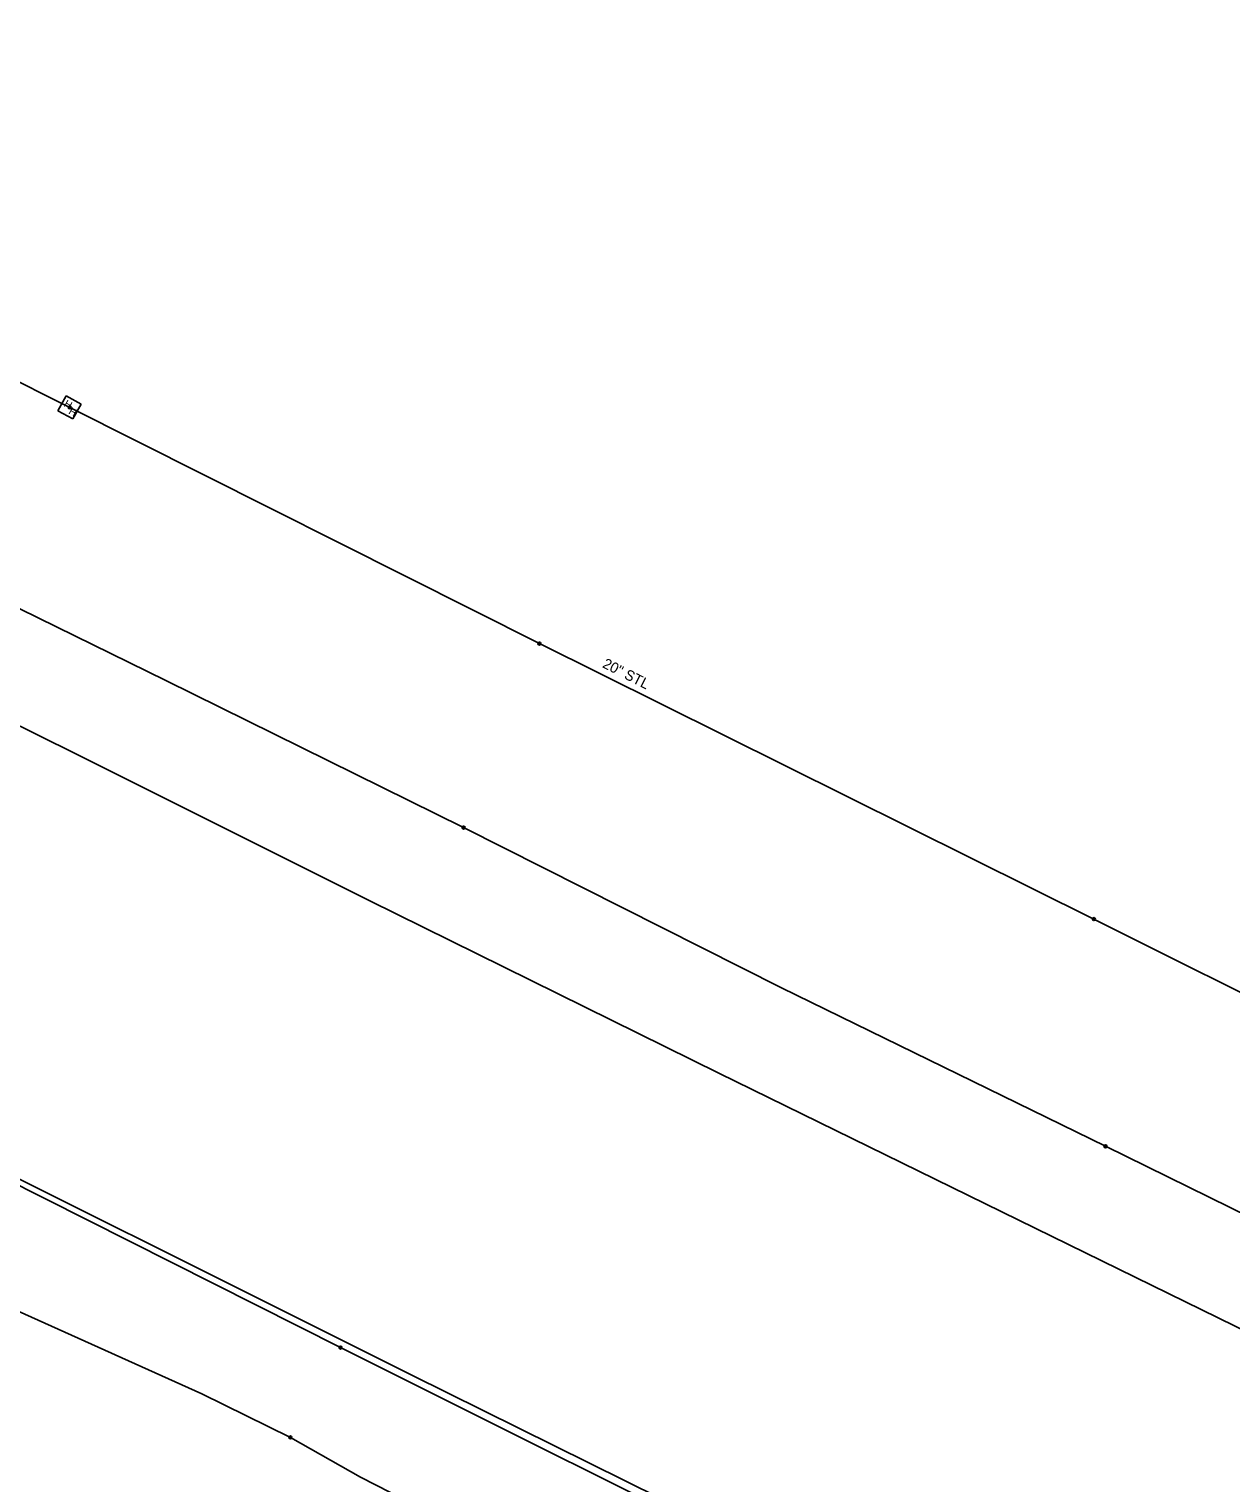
# Model space of a CAD drawing. Extents: x 2244485 to 2250986, y 199568 to 203007.
# Drawn here: x 2244898.9 to 2245302.1, y 202470.8 to 202958.5 of the extents above; entities that cross this region are included whole.
import ezdxf

# ---------------------------------------------------------------- set-up
doc = ezdxf.new("R2010")
doc.units = 0
for name, color, linetype in [('Default', 7, 'Continuous'), ('Exist Utilities Gas Meter CELL', 7, 'Continuous'), ('Exist Utilities Gas UG Line SUE LOS B', 7, 'Continuous'), ('Exist Utilities Gas UG Line SUE LOS B Text', 7, 'Continuous'), ('Exist Utilities Telephone UG Cable SUE LOS C', 7, 'Continuous'), ('Exist Utilities Telephone UG FO SUE LOS B', 7, 'Continuous'), ('Exist Utilities Telephone UG FO SUE LOS C', 7, 'Continuous')]:
    doc.layers.add(name, color=color, linetype=linetype)

# ---------------------------------------------------------------- blocks, each defined once
blk = doc.blocks.new('SurveyPointCell')
at = {"layer": 'Default'}
for p, q in [((-0.5, 0), (0.5, 0)), ((0, -0.5), (0, 0.5))]:
    blk.add_line(p, q, dxfattribs=at)
blk.add_circle((0, 0), 0.5, dxfattribs=at)

msp = doc.modelspace()

# ---------------------------------------------------------------- linework, layer by layer
at = {"layer": 'Exist Utilities Gas Meter CELL'}
for p, q in [((2244911.34, 202835.48), (2244908.57, 202830.47)), ((2244916.35, 202832.71), (2244911.34, 202835.48)), ((2244908.57, 202830.47), (2244913.59, 202827.7)), ((2244912.46, 202831.59), (2244912.46, 202831.59)), ((2244913.59, 202827.7), (2244916.35, 202832.71))]:
    msp.add_line(p, q, dxfattribs=at)
at = {"layer": 'Exist Utilities Gas UG Line SUE LOS B'}
msp.add_lwpolyline([(2244658.96, 202958.49), (2244721.96, 202928.3), (2244863.47, 202856.19), (2244912.51, 202831.57), (2245070.07, 202752.33), (2245256.14, 202659.91), (2245331.4, 202622.29), (2245514.38, 202531.76), (2245606.53, 202488.05), (2245652.12, 202465.42), (2245827.69, 202375.08), (2246001.01, 202291.84), (2246162.3, 202211.17), (2246329.12, 202125.74), (2246513.99, 202036.93), (2246642.7, 201974.75), (2246734.96, 201930.33), (2246858.92, 201868.26), (2246999.42, 201799.12), (2247177.53, 201710.71), (2247331.7, 201633.3), (2247466.92, 201567.22), (2247602.4, 201501.88), (2247749.1, 201426.01)], dxfattribs=at)
at = {"layer": 'Exist Utilities Telephone UG Cable SUE LOS C'}
msp.add_lwpolyline([(2244616.99, 202864.57), (2244821.95, 202761.17), (2244823.87, 202761.98), (2244826.85, 202767.1), (2244844.94, 202797.37), (2244826.91, 202761.73), (2244826.73, 202760.14), (2244827.76, 202758.24), (2244914.59, 202715.31), (2245013.24, 202666.09), (2245130.24, 202608.24), (2245342.53, 202504.23)], dxfattribs=at)
at = {"layer": 'Exist Utilities Telephone UG FO SUE LOS B'}
for points in [[(2244629.01, 202898.49), (2244702.01, 202861.79), (2244776.88, 202824.58), (2244852.79, 202784.99), (2244944.72, 202739.99), (2245044.67, 202690.62), (2245151.29, 202636.88), (2245260.01, 202583.68), (2245475.72, 202477.57)], [(2244549.31, 202739.15), (2244609.86, 202709.11), (2244677.79, 202678.26), (2244760.05, 202637.59), (2244890.2, 202573.21), (2245003.36, 202516.16), (2245157.86, 202439), (2245297.18, 202369.62), (2245354.5, 202340.75)], [(2244534.64, 202709.84), (2244609.27, 202669.97), (2244785.74, 202581.01), (2244840.19, 202553.14), (2244956.88, 202500.62), (2244986.55, 202486.03), (2245010.04, 202472.71), (2245040, 202457.4), (2245084.78, 202430.15), (2245170.23, 202380.19), (2245207.23, 202360.21), (2245246.97, 202340.05), (2245286.61, 202320.72), (2245320.18, 202303.77), (2245344.49, 202291.92), (2245347.99, 202287.98)]]:
    msp.add_lwpolyline(points, dxfattribs=at)
at = {"layer": 'Exist Utilities Telephone UG FO SUE LOS C'}
msp.add_lwpolyline([(2244555.09, 202740.38), (2244612.45, 202712.07), (2244680.5, 202678.83), (2244750.01, 202644.92), (2244809.78, 202614.66), (2244896.14, 202572.42), (2244969.14, 202536), (2245027.26, 202506.94), (2245218.26, 202412.25), (2245428.66, 202309.78), (2245606.8, 202219.11), (2245703.35, 202173.01), (2245852.59, 202097.7), (2245983.22, 202033.13), (2246107.4, 201971.58), (2246219.73, 201915.39), (2246355.16, 201847.48), (2246395.74, 201823.66), (2246448.95, 201797.92), (2246548.24, 201751.03)], dxfattribs=at)

# ---------------------------------------------------------------- block references
at = {"layer": 'Default'}
for p in [(2244912.51, 202831.57), (2245070.07, 202752.33), (2245044.67, 202690.62), (2245256.14, 202659.91), (2245260.01, 202583.68), (2245003.36, 202516.16), (2244986.55, 202486.03)]:
    msp.add_blockref('SurveyPointCell', p, dxfattribs=at)

# ---------------------------------------------------------------- texts
at = {"layer": 'Exist Utilities Gas Meter CELL'}
for p in [(2244910.35, 202832.08), (2244911.9, 202829.56)]:
    msp.add_text('H', height=2.5, rotation=331.0771, dxfattribs=at).set_placement(p)
at = {"layer": 'Exist Utilities Gas UG Line SUE LOS B Text'}
msp.add_text('20" STL', height=3.5, rotation=333.0915, dxfattribs=at).set_placement((2245090.99, 202744.48))

doc.saveas('drawing.dxf')
